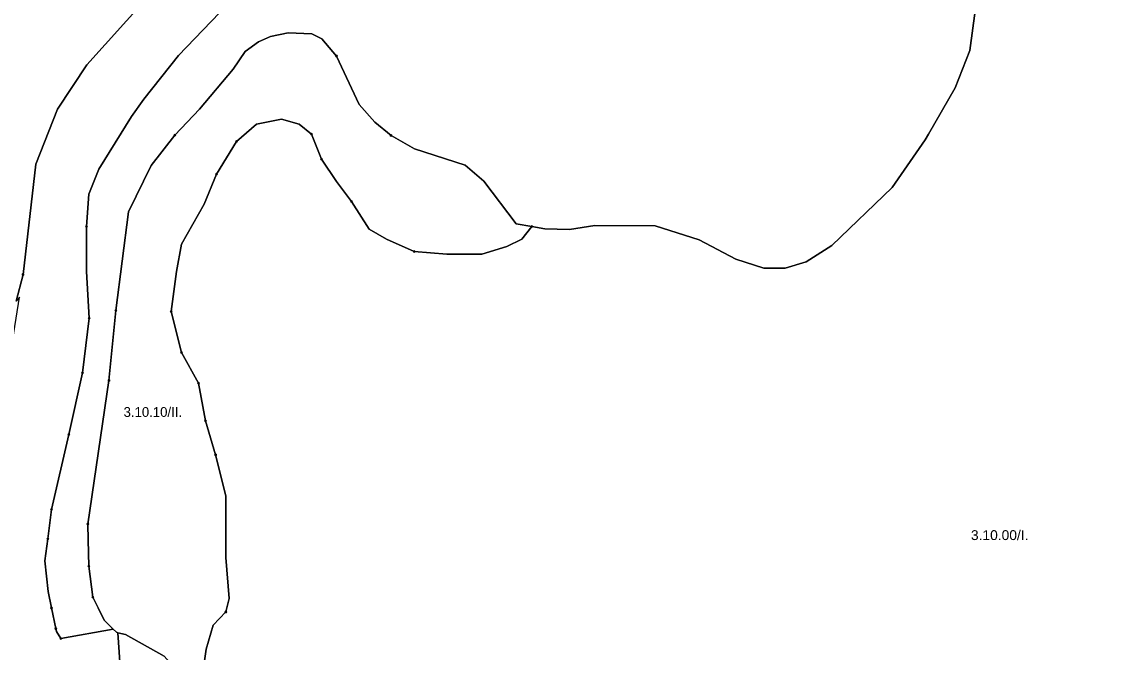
# Model space of a CAD drawing. Extents: x -650455 to -642254, y -1075222 to -1066610.
# Drawn here: x -645923 to -644814, y -1070045 to -1069403 of the extents above; entities that cross this region are included whole.
import ezdxf
from ezdxf.enums import TextEntityAlignment as Align

# ---------------------------------------------------------------- set-up
doc = ezdxf.new("R2010")
doc.units = 0
doc.header["$LTSCALE"] = 4
doc.header["$PDMODE"] = 32
doc.header["$PDSIZE"] = 2
for name, color, linetype, lineweight in [('1', 7, 'Continuous', 25), ('11', 7, 'Continuous', 13), ('12', 7, 'Continuous', 13), ('14', 7, 'Continuous', 13), ('15', 7, 'Continuous', 13)]:
    doc.layers.add(name, color=color, linetype=linetype, lineweight=lineweight)
doc.layers.add('2', color=7, linetype='Continuous')

msp = doc.modelspace()

# ---------------------------------------------------------------- linework, layer by layer
at = {"layer": '1'}
for points in [[(-645960, -1069928), (-645957.5, -1069916.501), (-645945.5, -1069826), (-645941.5, -1069786), (-645925, -1069683.5), (-645928.5, -1069687.5), (-645921.5, -1069660.5), (-645908.5, -1069548.001), (-645886.5, -1069492.001), (-645856.5, -1069447.001), (-645698.133, -1069270.881), (-645694.109, -1069269.277), (-645694.125, -1069269.251), (-645637, -1069246.5), (-645633.75, -1069245.251), (-645633.394, -1069245.058), (-645602, -1069232.501), (-645598.374, -1069232.751)], [(-645698.133, -1069270.881), (-645856.5, -1069447.001), (-645886.5, -1069492.001)], [(-645767, -1069518.5), (-645791, -1069549.5), (-645814, -1069596.501), (-645827, -1069697), (-645834, -1069768.5), (-645855.5, -1069914.5), (-645855.128, -1069930.498), (-645854.5, -1069957.501), (-645850.5, -1069989.001), (-645845.117, -1070000), (-645839, -1070012.5), (-645829.689, -1070021.439), (-645883.117, -1070031.08), (-645887.546, -1070024.046), (-645888.048, -1070021.037), (-645892.4, -1070000), (-645895.872, -1069983.218), (-645899.35, -1069951.919), (-645896.363, -1069929.516), (-645892.395, -1069899.754), (-645875.006, -1069823.246), (-645861.096, -1069760.648), (-645854.14, -1069705.005), (-645856.947, -1069657.538), (-645856.947, -1069611.709), (-645854.401, -1069578.61), (-645844.217, -1069553.15), (-645811.118, -1069499.682), (-645798.388, -1069481.86), (-645763.379, -1069437.622), (-645704.82, -1069376.516)], [(-645704.82, -1069376.516), (-645763.379, -1069437.622), (-645798.388, -1069481.86), (-645811.118, -1069499.682), (-645844.217, -1069553.15), (-645854.401, -1069578.61), (-645856.947, -1069611.709), (-645856.947, -1069657.538), (-645854.14, -1069705.005), (-645861.096, -1069760.648), (-645875.006, -1069823.246), (-645892.395, -1069899.754), (-645896.363, -1069929.516), (-645899.35, -1069951.919), (-645895.872, -1069983.218), (-645892.4, -1070000), (-645888.048, -1070021.037), (-645887.546, -1070024.046), (-645883.117, -1070031.08), (-645829.689, -1070021.439), (-645826.5, -1070024.5), (-645825.17, -1070025.403), (-645821.972, -1070069.724)], [(-644952.5, -1069392), (-644958, -1069432.5), (-644973, -1069470.5), (-645000, -1069517.419), (-645003.5, -1069523.501), (-645037, -1069572.001), (-645098.5, -1069631), (-645124.5, -1069647.5), (-645146, -1069654.001), (-645167.5, -1069654.001), (-645196, -1069645.001), (-645233.5, -1069625.001), (-645278, -1069611), (-645339.5, -1069610.5), (-645365.5, -1069614.5), (-645390.5, -1069614.001), (-645403.753, -1069611.715), (-645419.5, -1069609.001), (-645452.5, -1069565.501), (-645471.5, -1069549.001), (-645523, -1069532.501), (-645547, -1069519), (-645563.5, -1069505.5), (-645579.5, -1069487.501), (-645602.5, -1069438), (-645617.5, -1069420.5), (-645627.5, -1069415.501), (-645651.5, -1069414.501), (-645669.5, -1069418.001), (-645682, -1069423.501), (-645695.5, -1069433.5), (-645707.5, -1069451.501), (-645742, -1069492.001), (-645767, -1069518.5)], [(-645602.341, -1069565.88), (-645587.065, -1069586.248), (-645569.242, -1069614.255), (-645551.42, -1069624.439), (-645523.413, -1069637.17), (-645490.314, -1069639.716), (-645454.67, -1069639.716), (-645429.209, -1069632.077), (-645413.932, -1069624.439), (-645403.753, -1069611.715), (-645390.5, -1069614.001), (-645365.5, -1069614.5), (-645339.5, -1069610.5), (-645278, -1069611), (-645233.5, -1069625.001), (-645196, -1069645.001), (-645167.5, -1069654.001), (-645146, -1069654.001), (-645124.5, -1069647.5), (-645098.5, -1069631), (-645037, -1069572.001), (-645003.5, -1069523.501), (-645000, -1069517.419), (-644973, -1069470.5), (-644958, -1069432.5), (-644952.5, -1069392)], [(-645839, -1070012.5), (-645845.117, -1070000), (-645850.5, -1069989.001), (-645854.5, -1069957.501), (-645855.128, -1069930.498), (-645855.5, -1069914.5), (-645834, -1069768.5), (-645827, -1069697), (-645814, -1069596.501), (-645791, -1069549.5), (-645767, -1069518.5), (-645742, -1069492.001), (-645707.5, -1069451.501), (-645695.5, -1069433.5), (-645682, -1069423.501), (-645669.5, -1069418.001), (-645651.5, -1069414.501), (-645627.5, -1069415.501), (-645617.5, -1069420.5), (-645602.5, -1069438), (-645579.5, -1069487.501), (-645563.5, -1069505.5), (-645547, -1069519), (-645523, -1069532.501), (-645471.5, -1069549.001), (-645452.5, -1069565.501), (-645419.5, -1069609.001), (-645403.753, -1069611.715)], [(-645886.5, -1069492.001), (-645908.5, -1069548.001), (-645921.5, -1069660.5), (-645928.5, -1069687.5)], [(-645403.753, -1069611.715), (-645413.932, -1069624.439), (-645429.209, -1069632.077), (-645454.67, -1069639.716), (-645490.314, -1069639.716), (-645523.413, -1069637.17), (-645551.42, -1069624.439), (-645569.242, -1069614.255), (-645587.065, -1069586.248), (-645602.341, -1069565.88), (-645617.617, -1069542.965), (-645627.802, -1069517.505), (-645640.532, -1069507.32), (-645658.354, -1069502.228), (-645683.815, -1069507.32), (-645704.184, -1069525.143), (-645724.552, -1069558.242), (-645737.282, -1069588.794), (-645760.197, -1069629.531), (-645765.289, -1069657.538), (-645770.677, -1069698.05), (-645760.244, -1069739.782), (-645742.855, -1069771.081), (-645735.9, -1069809.335), (-645725.467, -1069844.112), (-645715.034, -1069885.843), (-645715.034, -1069948.441), (-645711.556, -1069990.173), (-645714.013, -1070000), (-645715.034, -1070004.084), (-645728.075, -1070017.56), (-645735.031, -1070041.903), (-645741.915, -1070090.098)], [(-645741.915, -1070090.098), (-645735.031, -1070041.903), (-645728.075, -1070017.56), (-645715.034, -1070004.084), (-645714.013, -1070000), (-645711.556, -1069990.173), (-645715.034, -1069948.441), (-645715.034, -1069885.843), (-645725.467, -1069844.112), (-645735.9, -1069809.335), (-645742.855, -1069771.081), (-645760.244, -1069739.782), (-645770.677, -1069698.05), (-645765.289, -1069657.538), (-645760.197, -1069629.531), (-645737.282, -1069588.794), (-645724.552, -1069558.242), (-645704.184, -1069525.143), (-645683.815, -1069507.32), (-645658.354, -1069502.228), (-645640.532, -1069507.32), (-645627.802, -1069517.505), (-645617.617, -1069542.965), (-645602.341, -1069565.88)], [(-645777.762, -1070048.899), (-645817.043, -1070027.048), (-645825.17, -1070025.403), (-645826.5, -1070024.5), (-645829.689, -1070021.439), (-645839, -1070012.5)], [(-645821.972, -1070069.724), (-645825.17, -1070025.403), (-645817.043, -1070027.048), (-645777.762, -1070048.899)]]:
    msp.add_lwpolyline(points, dxfattribs=at)
at = {"layer": '11'}
for p, q in [((-645742.855, -1069771.081), (-645735.9, -1069809.335)), ((-645735.9, -1069809.335), (-645725.467, -1069844.112))]:
    msp.add_line(p, q, dxfattribs=at)
for points in [[(-645941.5, -1069786), (-645925, -1069683.5), (-645928.5, -1069687.5), (-645921.5, -1069660.5), (-645908.5, -1069548.001), (-645886.5, -1069492.001), (-645856.5, -1069447.001), (-645698.133, -1069270.881), (-645695.195, -1069267.614), (-645695.188, -1069267.626), (-645687, -1069258.5), (-645636.5, -1069209.001), (-645431, -1069051.5), (-645370.25, -1069009.125)], [(-644810.5, -1069025), (-644836.38, -1069033.691), (-644871, -1069046.001), (-644887.558, -1069053.097), (-644888.516, -1069053.508), (-644917.772, -1069066.77), (-644932.672, -1069073.465), (-644937.5, -1069079.501), (-644948.5, -1069112.5), (-644954, -1069141), (-644954.5, -1069168.001), (-644950.5, -1069283.5), (-644952.5, -1069392), (-644958, -1069432.5), (-644973, -1069470.5), (-645000, -1069517.419), (-645003.5, -1069523.501), (-645037, -1069572.001), (-645098.5, -1069631), (-645124.5, -1069647.5), (-645146, -1069654.001), (-645167.5, -1069654.001)], [(-645627.802, -1069517.505), (-645640.532, -1069507.32), (-645658.354, -1069502.228), (-645683.815, -1069507.32), (-645704.184, -1069525.143), (-645724.552, -1069558.242)], [(-645587.065, -1069586.248), (-645602.341, -1069565.88), (-645617.617, -1069542.965), (-645627.802, -1069517.505)], [(-645724.552, -1069558.242), (-645737.282, -1069588.794), (-645760.197, -1069629.531), (-645765.289, -1069657.538), (-645770.677, -1069698.05), (-645760.244, -1069739.782), (-645742.855, -1069771.081)], [(-645403.753, -1069611.715), (-645413.932, -1069624.439), (-645429.209, -1069632.077), (-645454.67, -1069639.716), (-645490.314, -1069639.716), (-645523.413, -1069637.17), (-645551.42, -1069624.439), (-645569.242, -1069614.255), (-645587.065, -1069586.248)], [(-645167.5, -1069654.001), (-645196, -1069645.001), (-645233.5, -1069625.001), (-645278, -1069611), (-645339.5, -1069610.5), (-645365.5, -1069614.5), (-645390.5, -1069614.001), (-645403.753, -1069611.715)], [(-645725.467, -1069844.112), (-645715.034, -1069885.843), (-645715.034, -1069948.441), (-645711.556, -1069990.173), (-645714.013, -1070000), (-645715.034, -1070004.084), (-645728.075, -1070017.56), (-645735.031, -1070041.903), (-645741.915, -1070090.098), (-645726.5, -1070110.501), (-645703.5, -1070164.501), (-645696, -1070191.501), (-645694.628, -1070206.315), (-645696.21, -1070230.279), (-645696.21, -1070233.478), (-645696.21, -1070244.446), (-645693.219, -1070253.691)]]:
    msp.add_lwpolyline(points, dxfattribs=at)
for p in [(-645627.802, -1069517.505), (-645724.552, -1069558.242), (-645587.065, -1069586.248), (-645403.753, -1069611.715), (-645742.855, -1069771.081), (-645735.9, -1069809.335), (-645725.467, -1069844.112)]:
    msp.add_point(p, dxfattribs=at)
at = {"layer": '12'}
for p, q in [((-645724.552, -1069558.242), (-645704.184, -1069525.143)), ((-645760.244, -1069739.782), (-645770.677, -1069698.05)), ((-645854.5, -1069957.501), (-645850.5, -1069989.001))]:
    msp.add_line(p, q, dxfattribs=at)
for points in [[(-645602.5, -1069438), (-645617.5, -1069420.5), (-645627.5, -1069415.501), (-645651.5, -1069414.501), (-645669.5, -1069418.001), (-645682, -1069423.501), (-645695.5, -1069433.5), (-645707.5, -1069451.501), (-645742, -1069492.001), (-645767, -1069518.5)], [(-645547, -1069519), (-645563.5, -1069505.5), (-645579.5, -1069487.501), (-645602.5, -1069438)], [(-645704.184, -1069525.143), (-645683.815, -1069507.32), (-645658.354, -1069502.228), (-645640.532, -1069507.32), (-645627.802, -1069517.505), (-645617.617, -1069542.965)], [(-645767, -1069518.5), (-645791, -1069549.5), (-645814, -1069596.501), (-645827, -1069697), (-645834, -1069768.5), (-645855.5, -1069914.5)], [(-645523.413, -1069637.17), (-645490.314, -1069639.716), (-645454.67, -1069639.716), (-645429.209, -1069632.077), (-645413.932, -1069624.439), (-645403.753, -1069611.715), (-645419.5, -1069609.001), (-645452.5, -1069565.501), (-645471.5, -1069549.001), (-645523, -1069532.501), (-645547, -1069519)], [(-645617.617, -1069542.965), (-645602.341, -1069565.88), (-645587.065, -1069586.248), (-645569.242, -1069614.255), (-645551.42, -1069624.439), (-645523.413, -1069637.17)], [(-645770.677, -1069698.05), (-645765.289, -1069657.538), (-645760.197, -1069629.531), (-645737.282, -1069588.794), (-645724.552, -1069558.242)], [(-645735.9, -1069809.335), (-645742.855, -1069771.081), (-645760.244, -1069739.782)], [(-645715.034, -1070004.084), (-645714.013, -1070000), (-645711.556, -1069990.173), (-645715.034, -1069948.441), (-645715.034, -1069885.843), (-645725.467, -1069844.112), (-645735.9, -1069809.335)], [(-645855.5, -1069914.5), (-645855.128, -1069930.498), (-645854.5, -1069957.501)], [(-645850.5, -1069989.001), (-645845.117, -1070000), (-645839, -1070012.5), (-645829.689, -1070021.439), (-645826.5, -1070024.5), (-645825.17, -1070025.403), (-645817.043, -1070027.048), (-645777.762, -1070048.899), (-645757.472, -1070072.051), (-645741.915, -1070090.098), (-645735.031, -1070041.903), (-645728.075, -1070017.56), (-645715.034, -1070004.084)]]:
    msp.add_lwpolyline(points, dxfattribs=at)
for p in [(-645602.5, -1069438), (-645767, -1069518.5), (-645547, -1069519), (-645704.184, -1069525.143), (-645617.617, -1069542.965), (-645724.552, -1069558.242), (-645523.413, -1069637.17), (-645770.677, -1069698.05), (-645760.244, -1069739.782), (-645735.9, -1069809.335), (-645855.5, -1069914.5), (-645854.5, -1069957.501), (-645850.5, -1069989.001), (-645715.034, -1070004.084)]:
    msp.add_point(p, dxfattribs=at)
at = {"layer": '14'}
for p, q in [((-645834, -1069768.5), (-645827, -1069697)), ((-645861.096, -1069760.648), (-645875.006, -1069823.246)), ((-645892.4, -1070000), (-645888.048, -1070021.037))]:
    msp.add_line(p, q, dxfattribs=at)
for points in [[(-645704.82, -1069376.516), (-645763.379, -1069437.622), (-645798.388, -1069481.86), (-645811.118, -1069499.682), (-645844.217, -1069553.15), (-645854.401, -1069578.61), (-645856.947, -1069611.709)], [(-645471.5, -1069549.001), (-645452.5, -1069565.501), (-645419.5, -1069609.001), (-645403.753, -1069611.715), (-645390.5, -1069614.001), (-645365.5, -1069614.5), (-645339.5, -1069610.5), (-645278, -1069611), (-645233.5, -1069625.001), (-645196, -1069645.001), (-645167.5, -1069654.001), (-645146, -1069654.001), (-645124.5, -1069647.5), (-645098.5, -1069631), (-645037, -1069572.001), (-645003.5, -1069523.501), (-645000, -1069517.419), (-644973, -1069470.5), (-644958, -1069432.5), (-644952.5, -1069392)], [(-645827, -1069697), (-645814, -1069596.501), (-645791, -1069549.5), (-645767, -1069518.5), (-645742, -1069492.001), (-645707.5, -1069451.501), (-645695.5, -1069433.5), (-645682, -1069423.501), (-645669.5, -1069418.001), (-645651.5, -1069414.501), (-645627.5, -1069415.501), (-645617.5, -1069420.5), (-645602.5, -1069438), (-645579.5, -1069487.501), (-645563.5, -1069505.5), (-645547, -1069519), (-645523, -1069532.501), (-645471.5, -1069549.001)], [(-645856.947, -1069611.709), (-645856.947, -1069657.538), (-645854.14, -1069705.005), (-645861.096, -1069760.648)], [(-645888.048, -1070021.037), (-645887.546, -1070024.046), (-645883.117, -1070031.08), (-645829.689, -1070021.439), (-645839, -1070012.5), (-645845.117, -1070000), (-645850.5, -1069989.001), (-645854.5, -1069957.501), (-645855.128, -1069930.498), (-645855.5, -1069914.5), (-645834, -1069768.5)], [(-645875.006, -1069823.246), (-645892.395, -1069899.754), (-645896.363, -1069929.516)], [(-645896.363, -1069929.516), (-645899.35, -1069951.919), (-645895.872, -1069983.218), (-645892.4, -1070000)], [(-645777.762, -1070048.899), (-645817.043, -1070027.048), (-645825.17, -1070025.403), (-645821.972, -1070069.724)]]:
    msp.add_lwpolyline(points, dxfattribs=at)
for p in [(-645856.947, -1069611.709), (-645827, -1069697), (-645861.096, -1069760.648), (-645834, -1069768.5), (-645875.006, -1069823.246), (-645896.363, -1069929.516), (-645892.4, -1070000), (-645888.048, -1070021.037)]:
    msp.add_point(p, dxfattribs=at)
at = {"layer": '15'}
msp.add_line((-645892.395, -1069899.754), (-645875.006, -1069823.246), dxfattribs=at)
for points in [[(-645854.14, -1069705.005), (-645856.947, -1069657.538), (-645856.947, -1069611.709), (-645854.401, -1069578.61), (-645844.217, -1069553.15), (-645811.118, -1069499.682), (-645798.388, -1069481.86), (-645763.379, -1069437.622), (-645704.82, -1069376.516), (-645669.175, -1069333.233), (-645636.076, -1069289.95), (-645621.437, -1069268.627), (-645598.374, -1069232.751), (-645602, -1069232.501), (-645633.394, -1069245.058), (-645633.75, -1069245.251), (-645637, -1069246.5), (-645694.125, -1069269.251), (-645694.109, -1069269.277), (-645698.133, -1069270.881)], [(-645698.133, -1069270.881), (-645856.5, -1069447.001), (-645886.5, -1069492.001), (-645908.5, -1069548.001), (-645921.5, -1069660.5)], [(-645921.5, -1069660.5), (-645928.5, -1069687.5), (-645925, -1069683.5)], [(-645875.006, -1069823.246), (-645861.096, -1069760.648), (-645854.14, -1069705.005)], [(-645883.117, -1070031.08), (-645887.546, -1070024.046), (-645888.048, -1070021.037), (-645892.4, -1070000), (-645895.872, -1069983.218), (-645899.35, -1069951.919), (-645896.363, -1069929.516), (-645892.395, -1069899.754)], [(-645821.972, -1070069.724), (-645825.17, -1070025.403), (-645826.5, -1070024.5), (-645829.689, -1070021.439), (-645883.117, -1070031.08)]]:
    msp.add_lwpolyline(points, dxfattribs=at)
for p in [(-645921.5, -1069660.5), (-645854.14, -1069705.005), (-645875.006, -1069823.246), (-645892.395, -1069899.754), (-645883.117, -1070031.08)]:
    msp.add_point(p, dxfattribs=at)

# ---------------------------------------------------------------- texts
at = {"layer": '2'}
msp.add_text('3.10.10/II.', height=10, dxfattribs=at).set_placement((-645789.395, -1069805.446), align=Align.CENTER)
at = {"layer": '2', "width": 1.05}
msp.add_text('3.10.00/I.', height=10, dxfattribs=at).set_placement((-644927.532, -1069930.815), align=Align.CENTER)

doc.saveas('drawing.dxf')
